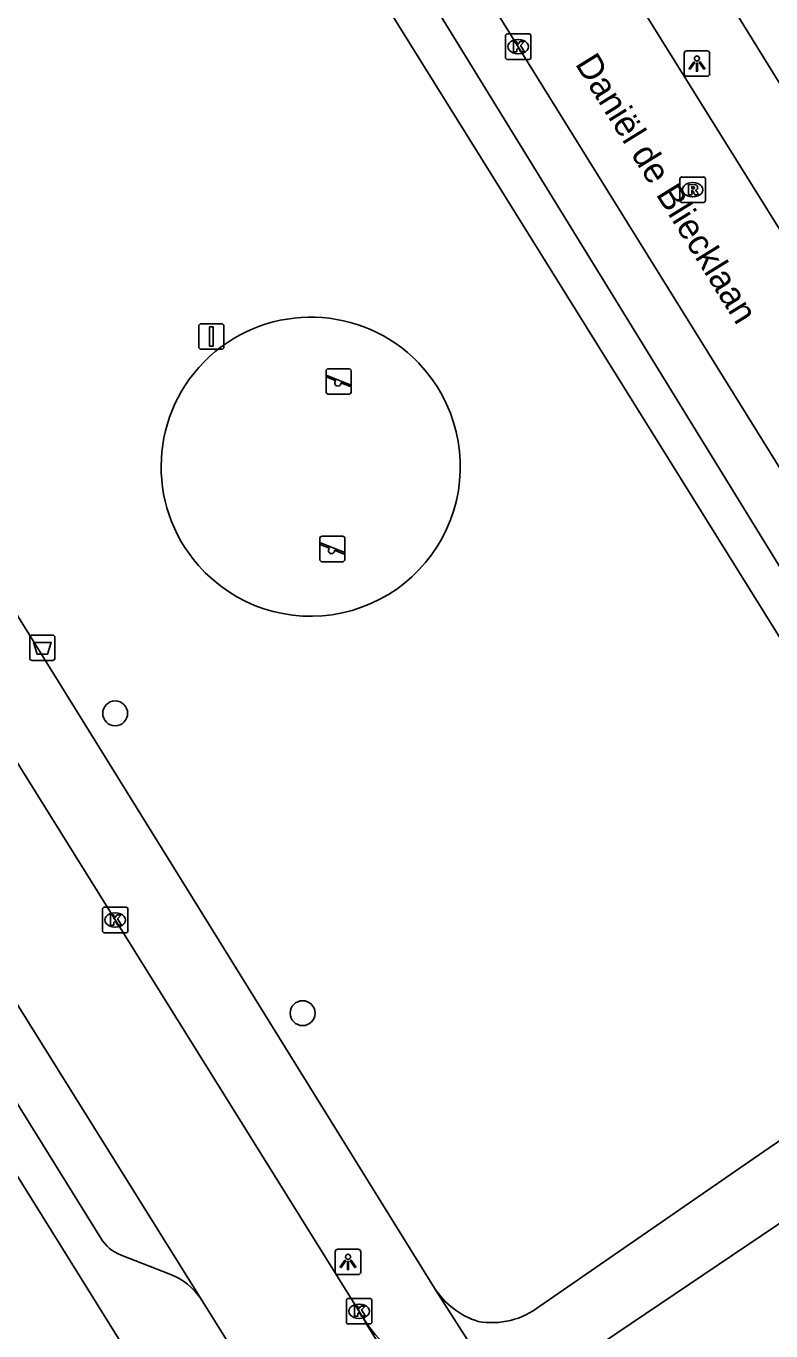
# Model space of a CAD drawing. Extents: x 160037 to 160839, y 385326 to 386441.
# Drawn here: x 160227.4 to 160256.6, y 386041.7 to 386092.9 of the extents above; entities that cross this region are included whole.
import ezdxf

# ---------------------------------------------------------------- set-up
doc = ezdxf.new("R2010")
doc.units = 0
for name, color, linetype in [('IMGEO_Afvalbak', 7, 'Continuous'), ('IMGEO_Boom', 7, 'Continuous'), ('IMGEO_Groenvoorziening', 7, 'Continuous'), ('IMGEO_Kolk', 7, 'Continuous'), ('IMGEO_Lichtpunt', 7, 'Continuous'), ('IMGEO_Openbare_ruimte_label', 7, 'Continuous'), ('IMGEO_Rijbaan_lokaal_open', 7, 'Continuous'), ('IMGEO_Rioolput', 7, 'Continuous'), ('IMGEO_Speelvoorziening', 7, 'Continuous'), ('IMGEO_Verkeersbordpaal', 7, 'Continuous'), ('IMGEO_Voetpad_open', 7, 'Continuous')]:
    doc.layers.add(name, color=color, linetype=linetype)

msp = doc.modelspace()

# ---------------------------------------------------------------- linework, layer by layer
at = {"layer": 'IMGEO_Afvalbak'}
for p, q in [((160227.558, 386068.078), (160227.558, 386068.878)), ((160227.558, 386068.878), (160227.558, 386068.078)), ((160227.658, 386068.978), (160228.448, 386068.978)), ((160228.448, 386068.978), (160227.658, 386068.978)), ((160228.548, 386068.878), (160228.548, 386068.078)), ((160228.548, 386068.078), (160228.548, 386068.878)), ((160228.448, 386067.978), (160227.658, 386067.978)), ((160227.658, 386067.978), (160228.448, 386067.978))]:
    msp.add_line(p, q, dxfattribs=at)
msp.add_lwpolyline([(160227.701, 386068.692), (160228.405, 386068.692), (160228.256, 386068.222), (160227.85, 386068.222), (160227.701, 386068.692)], dxfattribs=at)
for centre, start, end in [((160227.658, 386068.878), 90, 180), ((160227.658, 386068.878), 90, 180), ((160228.448, 386068.878), 0, 90), ((160228.448, 386068.878), 360, 90), ((160227.658, 386068.078), 180, 270), ((160227.658, 386068.078), 180, 270), ((160228.448, 386068.078), 270, 0), ((160228.448, 386068.078), 270, 0)]:
    msp.add_arc(centre, 0.1, start, end, dxfattribs=at)
at = {"layer": 'IMGEO_Boom'}
for centre in [(160230.91, 386065.905), (160238.266, 386054.137)]:
    msp.add_circle(centre, 0.489, dxfattribs=at)
at = {"layer": 'IMGEO_Groenvoorziening'}
for start, end in [(43.9035, 221.3177), (221.3185, 43.9027)]:
    msp.add_arc((160238.585, 386075.586), 5.87, start, end, dxfattribs=at)
at = {"layer": 'IMGEO_Kolk'}
for p, q in [((160246.301, 386092.574), (160247.153, 386092.574)), ((160246.226, 386091.648), (160246.226, 386092.5)), ((160246.714, 386092.354), (160246.739, 386092.354)), ((160247.227, 386092.5), (160247.227, 386091.648)), ((160247.153, 386091.574), (160246.301, 386091.574)), ((160246.737, 386091.794), (160246.712, 386091.794)), ((160230.486, 386058.295), (160231.338, 386058.295)), ((160230.411, 386057.369), (160230.411, 386058.221)), ((160230.899, 386058.075), (160230.924, 386058.075)), ((160231.412, 386058.221), (160231.412, 386057.369)), ((160231.338, 386057.295), (160230.486, 386057.295)), ((160230.922, 386057.515), (160230.897, 386057.515)), ((160240.059, 386042.938), (160240.911, 386042.938)), ((160239.984, 386042.012), (160239.984, 386042.864)), ((160240.472, 386042.718), (160240.497, 386042.718)), ((160240.985, 386042.864), (160240.985, 386042.012)), ((160240.911, 386041.938), (160240.059, 386041.938)), ((160240.495, 386042.158), (160240.47, 386042.158))]:
    msp.add_line(p, q, dxfattribs=at)
for points in [[(160246.301, 386092.574), (160247.153, 386092.574)], [(160246.226, 386091.648), (160246.226, 386092.5)], [(160246.547, 386092.274), (160246.67, 386092.274), (160246.67, 386092.123), (160246.8, 386092.274), (160246.964, 386092.274), (160246.818, 386092.123), (160246.971, 386091.874), (160246.819, 386091.874), (160246.734, 386092.038), (160246.67, 386091.971), (160246.67, 386091.874), (160246.547, 386091.874), (160246.547, 386092.274)], [(160247.227, 386092.5), (160247.227, 386091.648)], [(160247.153, 386091.574), (160246.301, 386091.574)], [(160230.486, 386058.295), (160231.338, 386058.295)], [(160230.411, 386057.369), (160230.411, 386058.221)], [(160230.732, 386057.995), (160230.855, 386057.995), (160230.855, 386057.844), (160230.985, 386057.995), (160231.149, 386057.995), (160231.003, 386057.844), (160231.156, 386057.595), (160231.004, 386057.595), (160230.919, 386057.759), (160230.855, 386057.692), (160230.855, 386057.595), (160230.732, 386057.595), (160230.732, 386057.995)], [(160231.412, 386058.221), (160231.412, 386057.369)], [(160231.338, 386057.295), (160230.486, 386057.295)], [(160240.059, 386042.938), (160240.911, 386042.938)], [(160239.984, 386042.012), (160239.984, 386042.864)], [(160240.305, 386042.638), (160240.428, 386042.638), (160240.428, 386042.487), (160240.558, 386042.638), (160240.722, 386042.638), (160240.576, 386042.487), (160240.729, 386042.238), (160240.577, 386042.238), (160240.492, 386042.402), (160240.428, 386042.335), (160240.428, 386042.238), (160240.305, 386042.238), (160240.305, 386042.638)], [(160240.985, 386042.864), (160240.985, 386042.012)], [(160240.911, 386041.938), (160240.059, 386041.938)]]:
    msp.add_lwpolyline(points, dxfattribs=at)
for centre, start, end in [((160246.303, 386092.498), 91.552, 178.448), ((160246.303, 386092.498), 91.552, 178.448), ((160247.151, 386092.498), 1.552, 88.448), ((160247.151, 386092.498), 1.552, 88.448), ((160246.303, 386091.65), 181.552, 268.448), ((160246.303, 386091.65), 181.552, 268.448), ((160247.151, 386091.65), 271.552, 358.448), ((160247.151, 386091.65), 271.552, 358.448), ((160230.488, 386058.219), 91.552, 178.448), ((160230.488, 386058.219), 91.552, 178.448), ((160231.336, 386058.219), 1.552, 88.448), ((160231.336, 386058.219), 1.552, 88.448), ((160230.488, 386057.371), 181.552, 268.448), ((160230.488, 386057.371), 181.552, 268.448), ((160231.336, 386057.371), 271.552, 358.448), ((160231.336, 386057.371), 271.552, 358.448), ((160240.061, 386042.862), 91.552, 178.448), ((160240.061, 386042.862), 91.552, 178.448), ((160240.909, 386042.862), 1.552, 88.448), ((160240.909, 386042.862), 1.552, 88.448), ((160240.061, 386042.014), 181.552, 268.448), ((160240.061, 386042.014), 181.552, 268.448), ((160240.909, 386042.014), 271.552, 358.448), ((160240.909, 386042.014), 271.552, 358.448)]:
    msp.add_arc(centre, 0.0765, start, end, dxfattribs=at)
for centre, major_axis, ratio, start_param, end_param in [((160246.713, 386092.074), (-0.387, 0.002), 0.722429, 4.712389, 7.853982), ((160246.738, 386092.074), (-0.39, 0.002), 0.717154, 1.570796, 4.712389), ((160230.898, 386057.795), (-0.387, 0.002), 0.722429, 4.712389, 7.853982), ((160230.923, 386057.795), (-0.39, 0.002), 0.717154, 1.570796, 4.712389), ((160240.471, 386042.438), (-0.387, 0.002), 0.722429, 4.712389, 7.853982), ((160240.496, 386042.438), (-0.39, 0.002), 0.717154, 1.570796, 4.712389)]:
    msp.add_ellipse(centre, major_axis=major_axis, ratio=ratio, start_param=start_param, end_param=end_param, dxfattribs=at)
at = {"layer": 'IMGEO_Lichtpunt'}
for p, q in [((160253.245, 386091.81), (160253.245, 386091.003)), ((160253.245, 386091.81), (160253.245, 386091.003)), ((160254.147, 386091.905), (160253.339, 386091.905)), ((160254.147, 386091.905), (160253.339, 386091.905)), ((160254.241, 386091.003), (160254.241, 386091.81)), ((160254.241, 386091.003), (160254.241, 386091.81)), ((160253.339, 386090.909), (160254.147, 386090.909)), ((160253.339, 386090.909), (160254.147, 386090.909)), ((160239.549, 386044.776), (160239.549, 386043.969)), ((160239.549, 386044.776), (160239.549, 386043.969)), ((160240.451, 386044.871), (160239.643, 386044.871)), ((160240.451, 386044.871), (160239.643, 386044.871)), ((160240.545, 386043.969), (160240.545, 386044.776)), ((160240.545, 386043.969), (160240.545, 386044.776)), ((160239.643, 386043.875), (160240.451, 386043.875)), ((160239.643, 386043.875), (160240.451, 386043.875))]:
    msp.add_line(p, q, dxfattribs=at)
for points in [[(160253.619, 386091.474), (160253.658, 386091.446), (160253.47, 386091.184), (160253.432, 386091.211), (160253.619, 386091.474)], [(160253.721, 386091.426), (160253.768, 386091.426), (160253.768, 386091.104), (160253.721, 386091.104), (160253.721, 386091.426)], [(160253.831, 386091.446), (160253.869, 386091.473), (160254.056, 386091.211), (160254.017, 386091.183), (160253.831, 386091.446)], [(160239.923, 386044.44), (160239.962, 386044.412), (160239.774, 386044.15), (160239.736, 386044.177), (160239.923, 386044.44)], [(160240.135, 386044.412), (160240.173, 386044.439), (160240.36, 386044.177), (160240.321, 386044.149), (160240.135, 386044.412)], [(160240.025, 386044.392), (160240.072, 386044.392), (160240.072, 386044.07), (160240.025, 386044.07), (160240.025, 386044.392)]]:
    msp.add_lwpolyline(points, dxfattribs=at)
for centre in [(160253.744, 386091.608), (160240.048, 386044.574)]:
    msp.add_circle(centre, 0.0994, dxfattribs=at)
for centre, start, end in [((160253.339, 386091.81), 90, 180), ((160253.339, 386091.81), 90, 180), ((160254.147, 386091.81), 0, 90), ((160254.147, 386091.81), 0, 90), ((160253.339, 386091.003), 180, 270), ((160253.339, 386091.003), 180, 270), ((160254.147, 386091.003), 270, 0), ((160254.147, 386091.003), 270, 360), ((160239.643, 386044.776), 90, 180), ((160239.643, 386044.776), 90, 180), ((160240.451, 386044.776), 0, 90), ((160240.451, 386044.776), 0, 90), ((160239.643, 386043.969), 180, 270), ((160239.643, 386043.969), 180, 270), ((160240.451, 386043.969), 270, 0), ((160240.451, 386043.969), 270, 360)]:
    msp.add_arc(centre, 0.0946, start, end, dxfattribs=at)
at = {"layer": 'IMGEO_Rijbaan_lokaal_open'}
for points in [[(160191.24, 386111.976), (160198.933, 386099.578), (160234.281, 386042.907)], [(160240.863, 386110.791), (160249.217, 386097.394), (160272.288, 386060.355)], [(160239.198, 386104.251), (160242.526, 386098.843), (160255.179, 386078.459), (160264.42, 386063.553)], [(160209.89, 386091.505), (160219.316, 386076.396), (160240.647, 386042.176)], [(160248.878, 386040.412), (160264.853, 386051.194)], [(160236.171, 386039.885), (160234.281, 386042.907)], [(160249.611, 386027.802), (160240.779, 386041.933), (160240.647, 386042.176)]]:
    msp.add_lwpolyline(points, dxfattribs=at)
msp.add_arc((160245.615, 386045.273), 5.855, 211.9412, 273.2285, dxfattribs=at)
at = {"layer": 'IMGEO_Rioolput'}
for p, q in [((160253.15, 386086.956), (160254.002, 386086.956)), ((160253.075, 386086.03), (160253.075, 386086.882)), ((160253.563, 386086.736), (160253.588, 386086.736)), ((160254.076, 386086.882), (160254.076, 386086.03)), ((160254.002, 386085.956), (160253.15, 386085.956)), ((160253.586, 386086.176), (160253.561, 386086.176))]:
    msp.add_line(p, q, dxfattribs=at)
for points in [[(160253.15, 386086.956), (160254.002, 386086.956)], [(160253.075, 386086.03), (160253.075, 386086.882)], [(160253.664, 386086.654), (160253.412, 386086.656), (160253.412, 386086.256)], [(160253.412, 386086.256), (160253.536, 386086.256), (160253.536, 386086.418), (160253.547, 386086.418)], [(160253.59, 386086.575), (160253.536, 386086.575), (160253.536, 386086.494)], [(160253.536, 386086.494), (160253.588, 386086.494)], [(160254.076, 386086.882), (160254.076, 386086.03)], [(160254.002, 386085.956), (160253.15, 386085.956)], [(160253.594, 386086.389), (160253.665, 386086.256), (160253.805, 386086.256), (160253.74, 386086.382)]]:
    msp.add_lwpolyline(points, dxfattribs=at)
for centre, radius, start, end in [((160253.152, 386086.88), 0.0765, 91.552, 178.448), ((160253.152, 386086.88), 0.0765, 91.552, 178.448), ((160254, 386086.88), 0.0765, 1.552, 88.448), ((160254, 386086.88), 0.0765, 1.552, 88.448), ((160253.546, 386086.365), 0.0533, 26.0293, 88.6989), ((160253.572, 386086.683), 0.19, 274.7715, 282.9687), ((160253.596, 386086.479), 0.0964, 77.0061, 93.1865), ((160253.61, 386086.536), 0.0378, 276.6634, 79.6772), ((160253.663, 386086.544), 0.109, 350.3612, 89.416), ((160253.661, 386086.544), 0.112, 277.5842, 350.9817), ((160253.645, 386086.329), 0.108, 29.5134, 73.7905), ((160253.152, 386086.032), 0.0765, 181.552, 268.448), ((160253.152, 386086.032), 0.0765, 181.552, 268.448), ((160254, 386086.032), 0.0765, 271.552, 358.448), ((160254, 386086.032), 0.0765, 271.552, 358.448)]:
    msp.add_arc(centre, radius, start, end, dxfattribs=at)
for centre, major_axis, ratio, start_param, end_param in [((160253.562, 386086.456), (-0.387, 0.002), 0.722429, 4.712389, 7.853982), ((160253.587, 386086.456), (-0.39, 0.002), 0.717154, 1.570796, 4.712389)]:
    msp.add_ellipse(centre, major_axis=major_axis, ratio=ratio, start_param=start_param, end_param=end_param, dxfattribs=at)
at = {"layer": 'IMGEO_Speelvoorziening'}
for p, q in [((160239.188, 386078.531), (160239.188, 386079.331)), ((160239.188, 386079.331), (160239.188, 386078.531)), ((160239.288, 386079.431), (160240.078, 386079.431)), ((160240.078, 386079.431), (160239.288, 386079.431)), ((160240.178, 386079.331), (160240.178, 386078.531)), ((160240.178, 386078.531), (160240.178, 386079.331)), ((160239.571, 386078.959), (160239.232, 386079.096)), ((160239.257, 386079.156), (160240.133, 386078.803)), ((160240.109, 386078.743), (160239.769, 386078.88)), ((160240.078, 386078.431), (160239.288, 386078.431)), ((160239.288, 386078.431), (160240.078, 386078.431)), ((160238.939, 386071.957), (160238.939, 386072.757)), ((160238.939, 386072.757), (160238.939, 386071.957)), ((160239.039, 386072.857), (160239.829, 386072.857)), ((160239.829, 386072.857), (160239.039, 386072.857)), ((160239.929, 386072.757), (160239.929, 386071.957)), ((160239.929, 386071.957), (160239.929, 386072.757)), ((160239.322, 386072.385), (160238.983, 386072.522)), ((160239.008, 386072.582), (160239.884, 386072.229)), ((160239.86, 386072.169), (160239.52, 386072.306)), ((160239.829, 386071.857), (160239.039, 386071.857)), ((160239.039, 386071.857), (160239.829, 386071.857))]:
    msp.add_line(p, q, dxfattribs=at)
for centre, radius, start, end in [((160239.288, 386079.331), 0.1, 90, 180), ((160239.288, 386079.331), 0.1, 90, 180), ((160240.078, 386079.331), 0.1, 0, 90), ((160240.078, 386079.331), 0.1, 360, 90), ((160239.245, 386079.126), 0.0327, 68.078, 248.078), ((160239.65, 386078.869), 0.12, 130.9928, 5.1632), ((160240.121, 386078.773), 0.0327, 248.078, 68.078), ((160239.288, 386078.531), 0.1, 180, 270), ((160239.288, 386078.531), 0.1, 180, 270), ((160240.078, 386078.531), 0.1, 270, 0), ((160240.078, 386078.531), 0.1, 270, 0), ((160239.039, 386072.757), 0.1, 90, 180), ((160239.039, 386072.757), 0.1, 90, 180), ((160239.829, 386072.757), 0.1, 0, 90), ((160239.829, 386072.757), 0.1, 360, 90), ((160238.996, 386072.552), 0.0327, 68.078, 248.078), ((160239.401, 386072.295), 0.12, 130.9928, 5.1632), ((160239.872, 386072.199), 0.0327, 248.078, 68.078), ((160239.039, 386071.957), 0.1, 180, 270), ((160239.039, 386071.957), 0.1, 180, 270), ((160239.829, 386071.957), 0.1, 270, 0), ((160239.829, 386071.957), 0.1, 270, 0)]:
    msp.add_arc(centre, radius, start, end, dxfattribs=at)
at = {"layer": 'IMGEO_Verkeersbordpaal'}
for p, q in [((160234.189, 386080.296), (160234.189, 386081.096)), ((160234.189, 386081.096), (160234.189, 386080.296)), ((160234.289, 386081.196), (160235.079, 386081.196)), ((160235.079, 386081.196), (160234.289, 386081.196)), ((160235.179, 386081.096), (160235.179, 386080.296)), ((160235.179, 386080.296), (160235.179, 386081.096)), ((160235.079, 386080.196), (160234.289, 386080.196)), ((160234.289, 386080.196), (160235.079, 386080.196))]:
    msp.add_line(p, q, dxfattribs=at)
msp.add_lwpolyline([(160234.609, 386081.071), (160234.759, 386081.071), (160234.759, 386080.321), (160234.609, 386080.321), (160234.609, 386081.071)], dxfattribs=at)
for centre, start, end in [((160234.289, 386081.096), 90, 180), ((160234.289, 386081.096), 90, 180), ((160235.079, 386081.096), 0, 90), ((160235.079, 386081.096), 360, 90), ((160234.289, 386080.296), 180, 270), ((160234.289, 386080.296), 180, 270), ((160235.079, 386080.296), 270, 0), ((160235.079, 386080.296), 270, 0)]:
    msp.add_arc(centre, 0.1, start, end, dxfattribs=at)
at = {"layer": 'IMGEO_Voetpad_open'}
for points in [[(160186.576, 386112.811), (160233.001, 386038.217)], [(160279.395, 386054.732), (160266.865, 386074.67), (160243.753, 386112.04)], [(160230.344, 386045.305), (160191.916, 386107.243)], [(160233.964, 386105.87), (160240.181, 386095.886), (160263.271, 386058.789), (160264.257, 386056.811)], [(160260.176, 386066.493), (160239.591, 386099.947)], [(160243.449, 386043.345), (160212.738, 386092.855)], [(160263.56, 386053.702), (160263.169, 386053.345), (160261.981, 386052.544), (160256.361, 386048.714), (160247.576, 386042.636)], [(160233.057, 386043.894), (160231.148, 386044.637)], [(160245.945, 386039.428), (160243.484, 386043.276), (160243.449, 386043.345)]]:
    msp.add_lwpolyline(points, dxfattribs=at)
for centre, radius, start, end in [((160231.752, 386046.182), 1.658, 211.9098, 248.6475), ((160232.116, 386041.474), 2.596, 33.4913, 68.7452), ((160246.087, 386045.019), 3.124, 212.3934, 252.5638), ((160245.694, 386045.054), 3.064, 259.8017, 307.9036)]:
    msp.add_arc(centre, radius, start, end, dxfattribs=at)

# ---------------------------------------------------------------- texts
at = {"layer": 'IMGEO_Openbare_ruimte_label'}
msp.add_text('Daniël de Bliecklaan', height=1, rotation=301.7989, dxfattribs=at).set_placement((160248.94, 386091.398))

doc.saveas('drawing.dxf')
